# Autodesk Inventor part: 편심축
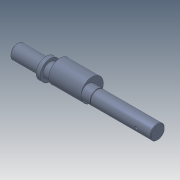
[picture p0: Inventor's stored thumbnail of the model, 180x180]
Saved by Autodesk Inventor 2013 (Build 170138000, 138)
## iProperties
Manager: 한국ATC센터
Company: 한국ATC센터
Created: 2014-10
Part Number: 편심축
Document SubType Name: Modeling
Designer: 한국ATC센터
Density: 7.86 g/cm^3
Material: 강, 연강
Mass: 1140.06 g
Surface Area: 226.679 cm^2
Volume: 145.046 cm^3
Author: KYOUNG IL JANG
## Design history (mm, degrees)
sketch "스케치1"
  geometry: L1 (-147, 0)-(147, 0); L2 (-147, 0)-(-147, 12.5); L3 (-147, 12.5)-(-47, 12.5); L4 (-47, 12.5)-(-47, 17.5); L5 (-47, 17.5)-(-40, 17.5); L6 (-40, 17.5)-(-40, 12.5); L7 (-40, 12.5)-(41.65, 12.5); L8 (41.65, 12.5)-(41.65, 11.95); L9 (41.65, 11.95)-(43, 11.95); L10 (43, 11.95)-(43, 12.5); L11 (43, 12.5)-(147, 12.5); L12 (147, 12.5)-(147, 0); L13 (114, 12.5)-(114, 9.1); L14 (114, 9.1)-(139, 9.1); L15 (139, 9.1)-(139, 12.5); L16 (122, -12.5)-(124.5, -12.5); L17 (124.5, -12.5)-(122, -10); L18 (122, -10)-(122, -12.5); L19 (-114, 12.5)-(-114, 9.1); L20 (-114, 9.1)-(-139, 9.1); L21 (-139, 9.1)-(-139, 12.5); L22 (-122, -12.5)-(-122, -10); L23 (-122, -10)-(-119.5, -12.5); L24 (-119.5, -12.5)-(-122, -12.5); 2 further points
  constraints: 48 end point, 11 parallel, 8 perpendicular, 5 collinear, 4 point on line, 1 coincident, 1 horizontal, 1 midpoint, 1 vertical
  dimensions: "d0" = 294 distance of L1.start L1.end (derived); "d1" = 25 diameter of L3 L1; "d2" = 35 diameter of L5 L1; "d3" = 100 distance of L2.end L3.end; "d4" = 187 distance between parallel lines of L12 L6; "d6" = 1.35 distance of L8.end L9.end; "d7" = 23.9 diameter of L9 L1; "d8" = 3.4 distance between parallel lines of L14 L11; "d9" = 8 distance between parallel lines of L15 L12; "d10" = 25 distance of L13.end L14.end; "d11" = 25 diameter of L16 L1 (= d1); "d12" = 25 distance from line of L12 L16.start; "d13" = 45 deg angle of L17 L18; "d14" = 5 diameter of L16.end L18; "d27" = 104 distance between parallel lines of L10 L12; "d32" = 7 distance of L4.end L5.end; "d33" = 8 distance between parallel lines of L2 L21; "d34" = 25 distance between parallel lines of L21 L19; "d35" = 3.4 distance between parallel lines of L3 L20; "d36" = 25 distance from line of L22.start L2; "d37" = 5 diameter of L23.end L22
revolve "회전1" stored, may be unused: angle "d15" = 90 deg
revolve "회전2" stored, may be unused: angle "d16" = 90 deg
revolve "회전3" stored, may be unused: angle "d38" = 90 deg
extrude "돌출1" cut sketch "스케치1" stored distance "d17" = 8; taper "d18" = 0 deg
fillet "모깎기1" dims "d19" = 4
node "작업 평면1"
sketch "스케치2"
  geometry: C1 r 12.5 at (0, 0) reference; C2 r 19.5 at (0, 7); 1 further point
  constraints: 1 centre point, 1 tangent, 1 vertical alignment
  dimensions: "d21" = 7 distance of point (0, 0) C2.centre; "d30" = 39 diameter of C2 (derived)
extrude "돌출2" join sketch "스케치2" distance "d22" = 56; taper "d23" = 0 deg
chamfer "모따기1" distance "d24" = 1; stored, may be unused: second distance "d25" = 2, angle "d26" = 45 deg
node "솔리드1"
